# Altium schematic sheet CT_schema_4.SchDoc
size 334 x 183 mm
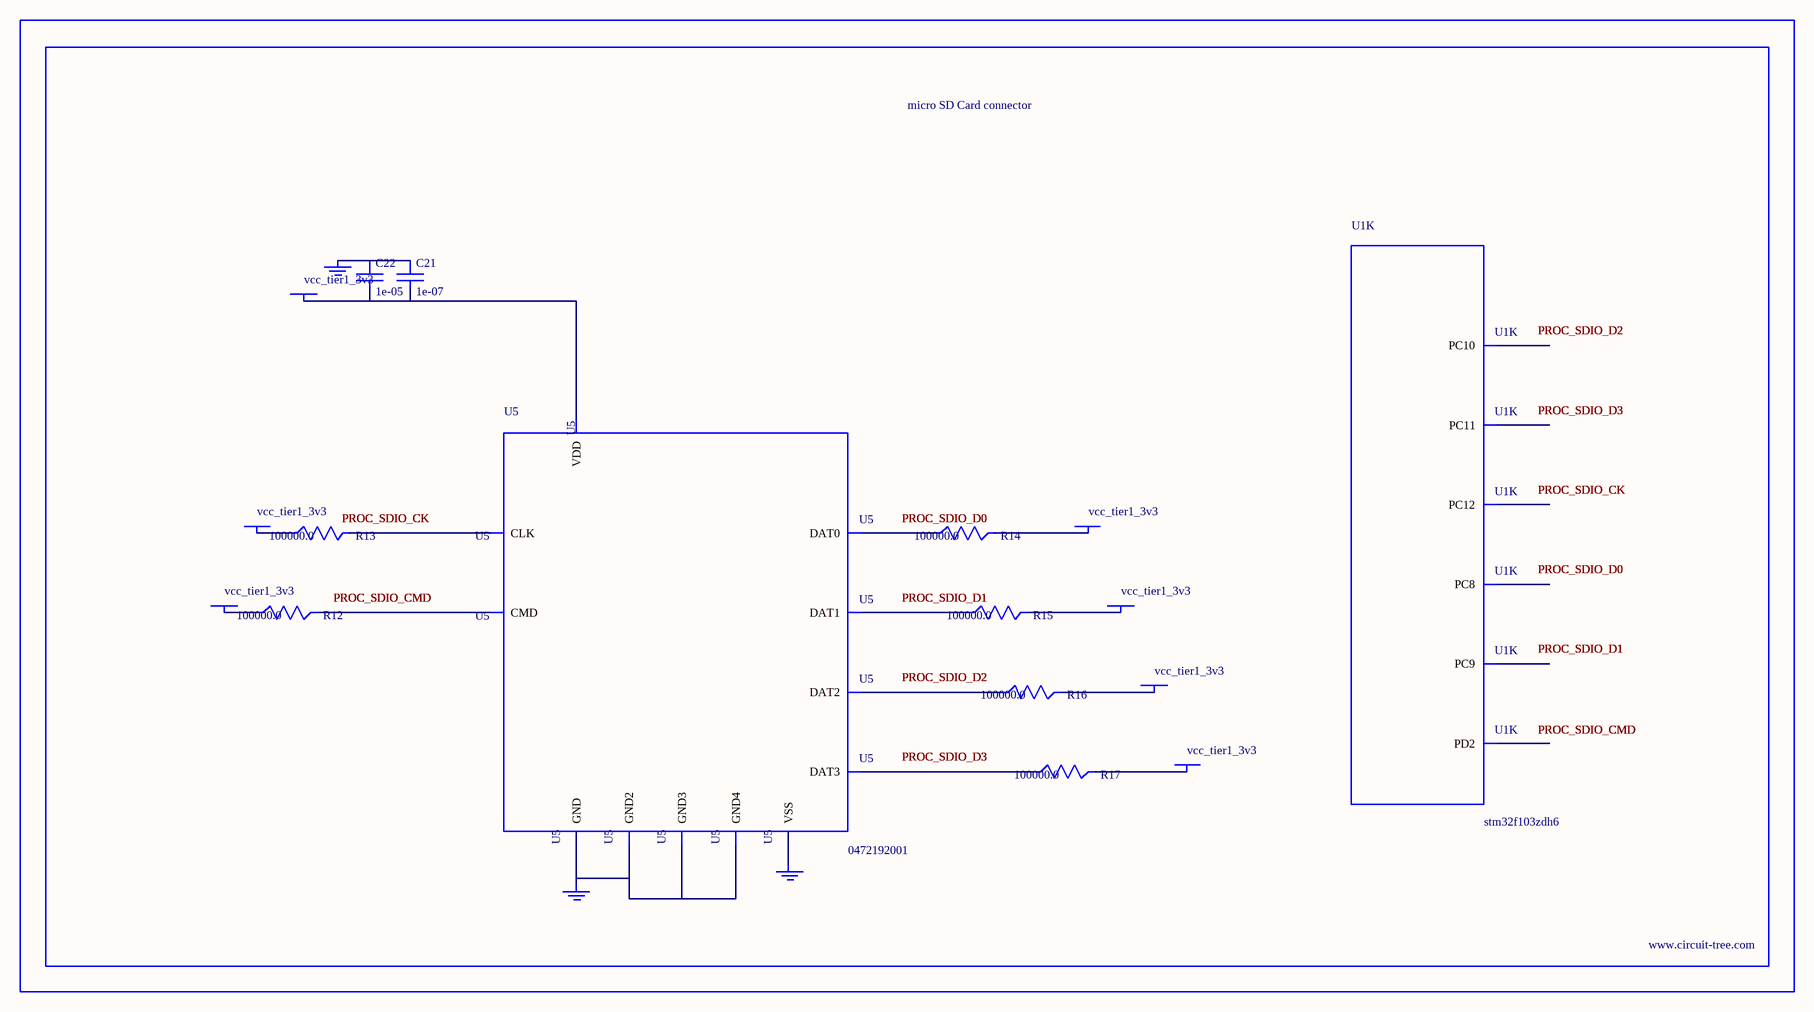
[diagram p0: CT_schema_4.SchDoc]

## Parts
BORDER3  (no value)
C21  1e-07  [C0402]
C22  1e-05  [C0805]
GND_INSTANCE_3_0  (no value)
GND_INSTANCE_3_1  (no value)
GND_INSTANCE_3_2  (no value)
POWER_INSTANCE_3_0  vcc_tier1_3v3
POWER_INSTANCE_3_1  vcc_tier1_3v3
POWER_INSTANCE_3_2  vcc_tier1_3v3
POWER_INSTANCE_3_3  vcc_tier1_3v3
POWER_INSTANCE_3_4  vcc_tier1_3v3
POWER_INSTANCE_3_5  vcc_tier1_3v3
POWER_INSTANCE_3_6  vcc_tier1_3v3
R12  100000.0  [R0603]
R13  100000.0  [R0603]
R14  100000.0  [R0603]
R15  100000.0  [R0603]
R16  100000.0  [R0603]
R17  100000.0  [R0603]
U1  stm32f103zdh6  [LFBGA144]  (part K of 12)
U5  0472192001  [MOLEX_47219-2001]

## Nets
NetC21_1: C21.1 C22.1 GND_INSTANCE_3_0.0(GND)
NetC21_2: C21.2 C22.2 POWER_INSTANCE_3_3.0(PWR) U5.4(VDD)
NetGND_INSTANCE_3_1_0: GND_INSTANCE_3_1.0(GND) U5.6(VSS)
NetGND_INSTANCE_3_2_0: GND_INSTANCE_3_2.0(GND) U5.G1(GND) U5.G2(GND2) U5.G3(GND3) U5.G4(GND4)
NetPOWER_INSTANCE_3_0_0: POWER_INSTANCE_3_0.0(PWR) R16.2
NetPOWER_INSTANCE_3_1_0: POWER_INSTANCE_3_1.0(PWR) R17.2
NetPOWER_INSTANCE_3_2_0: POWER_INSTANCE_3_2.0(PWR) R12.1
NetPOWER_INSTANCE_3_4_0: POWER_INSTANCE_3_4.0(PWR) R13.1
NetPOWER_INSTANCE_3_5_0: POWER_INSTANCE_3_5.0(PWR) R14.2
NetPOWER_INSTANCE_3_6_0: POWER_INSTANCE_3_6.0(PWR) R15.2
NetR12_2: R12.2 U5.3(CMD)
NetR13_2: R13.2 U5.5(CLK)
NetR14_1: R14.1 U5.7(DAT0)
NetR15_1: R15.1 U5.8(DAT1)
NetR16_1: R16.1 U5.1(DAT2)
NetR17_1: R17.1 U5.2(DAT3)

Not connected (* = marked no-connect by the designer): U1 B10(PC11) B11(PC10) C10(PC12) E9(PD2) E11(PC9) F11(PC8)

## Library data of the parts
BORDER3 = BORDER_PAGE3
C21 = C0402C104K3RACTU
C22 = C0805C106K8RACTU
GND_INSTANCE_3_0-GND_INSTANCE_3_2 = GND
POWER_INSTANCE_3_0-POWER_INSTANCE_3_6 = PWR
R12-R17 = RC0603JR-07100KL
